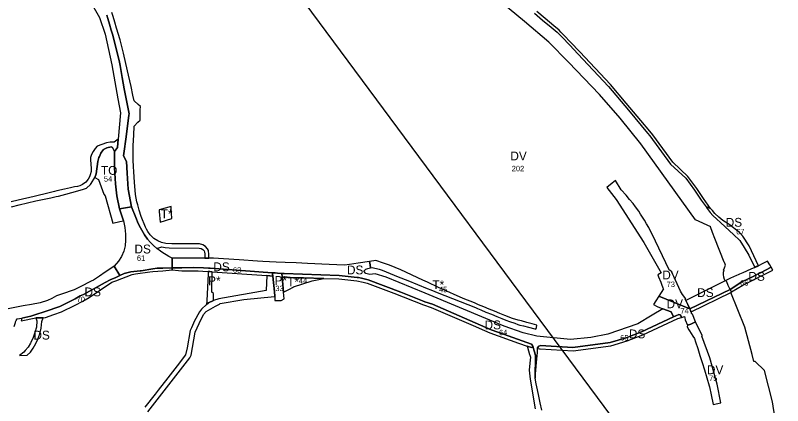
# Model space of a CAD drawing. Extents: x -535435 to -532834, y -1165802 to -1163866.
# Drawn here: x -534109 to -532979, y -1165015 to -1164441 of the extents above; entities that cross this region are included whole.
import ezdxf

# ---------------------------------------------------------------- set-up
doc = ezdxf.new("R2010")
doc.units = 0
for name, color, linetype in [('Level 14', 7, 'Continuous'), ('Level 15', 7, 'Continuous'), ('Level 22', 7, 'Continuous'), ('Level 23', 7, 'Continuous'), ('Level 35', 7, 'Continuous'), ('Level 4', 7, 'Continuous'), ('Level 43', 7, 'Continuous'), ('Level 44', 7, 'Continuous'), ('Level 5', 7, 'Continuous'), ('Level 61', 7, 'Continuous'), ('Level 62', 7, 'Continuous')]:
    doc.layers.add(name, color=color, linetype=linetype)

msp = doc.modelspace()

# ---------------------------------------------------------------- linework, layer by layer
at = {"layer": 'Level 14'}
for points in [[(-533157.8, -1164819.3), (-533163, -1164822.5), (-533161.8, -1164825.5), (-533158.7, -1164833.2), (-533157, -1164837.5), (-533154.9, -1164842.7), (-533154.8, -1164843.1), (-533161.7, -1164853.8), (-533116, -1164872.2), (-533119, -1164865.8), (-533121.8, -1164860.1), (-533122.6, -1164858.4), (-533121.9, -1164858.1), (-533122.4, -1164857), (-533124.5, -1164853.6), (-533126.8, -1164851.2), (-533129.8, -1164846.5), (-533139.4, -1164824.7), (-533143.2, -1164816.8), (-533143.6, -1164816.3), (-533144.3, -1164816), (-533144.6, -1164815.9), (-533145.2, -1164816), (-533145.7, -1164816), (-533171.8, -1164761.4), (-533174.1, -1164756.9), (-533176.4, -1164752.7), (-533179.5, -1164747.3), (-533182.7, -1164741.9), (-533185.3, -1164737.6), (-533188.4, -1164732.9), (-533191.1, -1164728.8), (-533195.7, -1164722.5), (-533199.4, -1164717.5), (-533204.4, -1164711.3), (-533209.4, -1164705.3), (-533216.8, -1164697.2), (-533225.2, -1164683.8), (-533230.1, -1164687.7), (-533238.1, -1164694.1), (-533224.1, -1164711.6), (-533183.3, -1164774.7), (-533157.8, -1164819.3)], [(-533128.7, -1164883.8), (-533127.9, -1164885.1), (-533123.8, -1164883.9), (-533123.2, -1164885.5), (-533122.9, -1164888.8), (-533119.4, -1164896.4), (-533114.4, -1164894.8), (-533107.5, -1164891.5), (-533111.8, -1164880.4), (-533113, -1164880.4), (-533113.9, -1164876.6), (-533114.4, -1164876.7), (-533114.8, -1164874.6), (-533116, -1164872.2), (-533161.7, -1164853.8), (-533166.1, -1164860.6), (-533169.3, -1164865.8), (-533163.8, -1164869.1), (-533155.4, -1164872.4), (-533143.4, -1164877), (-533140, -1164884.3), (-533136.5, -1164882.7), (-533131.8, -1164880.8), (-533130.3, -1164881.4), (-533128.7, -1164883.8)], [(-533114.4, -1164894.8), (-533119.4, -1164896.4), (-533119.8, -1164898.8), (-533117.1, -1164903.2), (-533116.1, -1164904.8), (-533111.3, -1164912.7), (-533109, -1164916.2), (-533107.5, -1164920.9), (-533104.3, -1164930.9), (-533100.9, -1164941.1), (-533097.7, -1164951.2), (-533094.4, -1164962.4), (-533090.9, -1164974.1), (-533087.4, -1164985.8), (-533086.9, -1164987.3), (-533084.4, -1164999), (-533081.3, -1165013.3), (-533070.4, -1165010.8), (-533075.7, -1164983.3), (-533086.4, -1164944.6), (-533098.1, -1164912.4), (-533097.9, -1164912.1), (-533097.9, -1164911.7), (-533107.5, -1164891.5), (-533114.4, -1164894.8)]]:
    msp.add_lwpolyline(points, dxfattribs=at)
at = {"layer": 'Level 15'}
for points in [[(-533682.6, -1164422.5), (-533200.4, -1165073.2)], [(-532979.2, -1165103.8), (-532994.2, -1165009), (-533005.9, -1164963.1), (-533019.7, -1164949.8), (-533021.6, -1164949.8), (-533024.3, -1164939.5), (-533035, -1164899.4), (-533055.7, -1164848.2), (-533054.7, -1164847.5), (-533056.5, -1164843.9), (-533059.2, -1164838), (-533061.6, -1164832.9), (-533061.9, -1164832.2), (-533062.2, -1164831.9), (-533062.6, -1164831.5), (-533063, -1164831.4), (-533063.6, -1164831.4), (-533064.6, -1164829.3), (-533065.9, -1164825.9), (-533066.3, -1164821.8), (-533066.1, -1164818.4), (-533065.5, -1164815.5), (-533066.1, -1164815.3), (-533065, -1164812.3), (-533063.4, -1164808), (-533063.8, -1164806.8), (-533064.8, -1164804.1), (-533065.3, -1164803.8), (-533079, -1164768.7), (-533082.4, -1164760), (-533085.4, -1164751.9), (-533085.1, -1164751.8), (-533107.7, -1164741.3), (-533187.9, -1164629.8), (-533218.6, -1164591.9), (-533248.9, -1164557.2), (-533294.4, -1164509.7), (-533323.6, -1164480.2), (-533359.3, -1164449.4), (-533393, -1164421.7)]]:
    msp.add_lwpolyline(points, dxfattribs=at)
at = {"layer": 'Level 22'}
msp.add_lwpolyline([(-533895.6, -1164744.9), (-533878.2, -1164739.7), (-533879.3, -1164723.8), (-533879.5, -1164721.7), (-533897, -1164726.7), (-533896.8, -1164729.2), (-533895.6, -1164744.9)], dxfattribs=at)
at = {"layer": 'Level 23'}
for points in [[(-533541.2, -1164814.8), (-533558, -1164808.3), (-533563.9, -1164806), (-533566.5, -1164805), (-533577.8, -1164801.3), (-533587.3, -1164802.7), (-533586.5, -1164807.8), (-533585.8, -1164812.2), (-533583.6, -1164811.6), (-533573.3, -1164813.9), (-533568.8, -1164815.7), (-533545.2, -1164825.2), (-533531.1, -1164830.9), (-533502.4, -1164842.5), (-533497.2, -1164844.5), (-533491.2, -1164846.9), (-533487.7, -1164848.3), (-533431.5, -1164870.6), (-533428.4, -1164871.8), (-533423.5, -1164873.9), (-533415.9, -1164877.1), (-533408, -1164880.3), (-533400.1, -1164883.6), (-533392.6, -1164886.7), (-533386.5, -1164889.3), (-533381.4, -1164891), (-533373.5, -1164893.7), (-533369.1, -1164895.3), (-533366, -1164896.3), (-533360.9, -1164897.6), (-533353.2, -1164899.6), (-533343.8, -1164902), (-533342.3, -1164902.3), (-533341.7, -1164900), (-533340.8, -1164896.5), (-533348, -1164894.6), (-533355.6, -1164892.4), (-533363.8, -1164890.2), (-533368.5, -1164888.9), (-533376.8, -1164886.6), (-533387.9, -1164882.2), (-533395.4, -1164879.2), (-533403.4, -1164875.9), (-533411.2, -1164872.7), (-533418.9, -1164869.5), (-533426.8, -1164866.3), (-533432.8, -1164863.8), (-533449.3, -1164857), (-533482.5, -1164842.7), (-533486, -1164841.2), (-533502.2, -1164833.4), (-533508.9, -1164830.2)], [(-533700.8, -1164841.2), (-533699, -1164840.2), (-533671.6, -1164831.2), (-533654.5, -1164827.9), (-533684.5, -1164827), (-533699.2, -1164826.6), (-533708.7, -1164825.9), (-533716.1, -1164825.2), (-533716.1, -1164825.6), (-533715.5, -1164831), (-533713.8, -1164847.9), (-533704.3, -1164843)]]:
    msp.add_lwpolyline(points, close=True, dxfattribs=at)
for points in [[(-533913.8, -1165024), (-533851.8, -1164944.7), (-533849.7, -1164940.5), (-533844, -1164906.5), (-533838.2, -1164893.8), (-533831.5, -1164880.8), (-533827.7, -1164876.4), (-533824.4, -1164874.4), (-533814.1, -1164868.4), (-533808.3, -1164865.4), (-533807.2, -1164864.8), (-533772.1, -1164858.7), (-533727.2, -1164854.1), (-533726.9, -1164854), (-533727.1, -1164847.2), (-533729.7, -1164824.1), (-533738.7, -1164823.4), (-533739.5, -1164845.6), (-533809.3, -1164857.5), (-533817.2, -1164860), (-533824.2, -1164863.4), (-533827.2, -1164866), (-533834.5, -1164872.8), (-533837.8, -1164876.6), (-533845.2, -1164891.1), (-533846.2, -1164893.4), (-533849.3, -1164900.2), (-533851.2, -1164904.2), (-533855.5, -1164929.8), (-533858.2, -1164940.3), (-533870.5, -1164956.3), (-533884.3, -1164974.1), (-533898.2, -1164991.9), (-533902.8, -1164997.8), (-533918, -1165017.2)], [(-533333.9, -1165021.4), (-533336.2, -1165010.6), (-533338.2, -1165000.7), (-533340.1, -1164991.5), (-533340.1, -1164991.4), (-533341.9, -1164982.7), (-533343.6, -1164974.3), (-533343.3, -1164963.3), (-533343.1, -1164953), (-533342.9, -1164942.2), (-533342.8, -1164941), (-533344.5, -1164935.7), (-533345.5, -1164932.6), (-533346.6, -1164929), (-533349, -1164929.4), (-533355.4, -1164927.2), (-533354.9, -1164928.8), (-533353.4, -1164934.1), (-533351.9, -1164939.4), (-533351.3, -1164940.6), (-533350.5, -1164943.4), (-533351.3, -1164952.5), (-533352.3, -1164962.6), (-533350.7, -1164975.8), (-533343.4, -1165019.3)]]:
    msp.add_lwpolyline(points, dxfattribs=at)
at = {"layer": 'Level 35'}
msp.add_lwpolyline([(-533965.3, -1164746.5), (-533954.8, -1164744.1), (-533949.6, -1164742.7), (-533955.1, -1164725.1), (-533959.3, -1164706.1), (-533961.1, -1164688.5), (-533962.5, -1164664.9), (-533962.8, -1164640.9), (-533965.8, -1164634.9), (-533967.7, -1164634.1), (-533974.1, -1164635.7), (-533978.8, -1164638.2), (-533981.7, -1164641.9), (-533982.7, -1164643.3), (-533984.8, -1164648.1), (-533985.6, -1164649.9), (-533987.1, -1164655.7), (-533989.6, -1164674), (-533991.8, -1164679.4), (-533986.3, -1164682.3), (-533978.2, -1164703.6), (-533976.6, -1164706.2)], close=True, dxfattribs=at)
at = {"layer": 'Level 4'}
for points in [[(-533999.9, -1164416.7), (-533984.7, -1164443.9), (-533976.4, -1164468.5), (-533966.5, -1164513.4), (-533957.7, -1164563.2), (-533953.9, -1164584.2), (-533957.2, -1164622.7), (-533958.2, -1164634.9), (-533962.8, -1164640.9), (-533962.5, -1164664.9), (-533961.1, -1164688.5), (-533959.3, -1164706.1), (-533955.1, -1164725.1), (-533937.6, -1164722.1), (-533942.5, -1164696.4), (-533942.9, -1164688.7), (-533943.8, -1164672.8), (-533944.8, -1164655.5), (-533949.2, -1164647.3), (-533948.7, -1164643.8), (-533945.6, -1164619.4), (-533941.6, -1164587.6), (-533941.3, -1164585.4), (-533948.6, -1164548.8), (-533951.4, -1164531.9), (-533954.4, -1164514.2), (-533955.2, -1164509.4), (-533962.7, -1164479.5), (-533965.5, -1164468.5), (-533967.4, -1164462.2), (-533970.1, -1164453.5), (-533972.7, -1164445.1), (-533974.2, -1164440.1)], [(-533092, -1164722.5), (-533088.7, -1164723.5), (-533085.2, -1164724.6), (-533095.7, -1164710.1), (-533105.4, -1164695.3), (-533118.6, -1164677.5), (-533141.1, -1164656.7), (-533170.5, -1164616.2), (-533174.7, -1164611.1), (-533188, -1164595.1), (-533209.4, -1164569.6), (-533232.5, -1164542.4), (-533277.6, -1164494.1), (-533291.3, -1164479.8), (-533300.6, -1164470.2), (-533305.5, -1164465.1), (-533308.4, -1164462.2), (-533315.9, -1164455.9), (-533328.8, -1164445.2), (-533340.8, -1164435.1)], [(-533344.4, -1164437.6), (-533332.5, -1164447.6), (-533320, -1164457.9), (-533311.3, -1164465.2), (-533309.6, -1164467), (-533304.4, -1164472.4), (-533292.7, -1164484.5), (-533280.6, -1164497), (-533235.7, -1164545.2), (-533205.9, -1164580.3), (-533177.9, -1164613.7), (-533174.6, -1164617.7), (-533144.2, -1164659.5), (-533121.7, -1164680.3), (-533108.9, -1164697.7), (-533099.2, -1164712.5), (-533092, -1164722.5)], [(-534067.7, -1164885.4), (-534078.3, -1164885.8), (-534077, -1164890.2), (-534077.7, -1164899.3), (-534079.8, -1164907), (-534082.4, -1164914.6), (-534085.7, -1164921.9), (-534086.5, -1164923.1), (-534089.9, -1164928.7), (-534094, -1164933.8), (-534095.9, -1164936), (-534102.6, -1164940.9), (-534091.4, -1164940.5), (-534086.4, -1164936.4), (-534082.2, -1164930.5), (-534078.3, -1164923.3), (-534075.5, -1164917), (-534072.8, -1164909.2), (-534070.4, -1164900.7), (-534069.4, -1164890.9), (-534067.7, -1164885.4)]]:
    msp.add_lwpolyline(points, dxfattribs=at)
for points in [[(-533872.6, -1164797.7), (-533877.6, -1164797.7), (-533877.6, -1164812.2), (-533863.4, -1164811.9), (-533845.9, -1164811.5), (-533831.8, -1164811.9), (-533824.1, -1164812.4), (-533821.7, -1164812.6), (-533730.5, -1164819.2), (-533726, -1164819.6), (-533722.7, -1164819.8), (-533716.6, -1164820.2), (-533712.8, -1164820.5), (-533632, -1164823.5), (-533605.3, -1164826.1), (-533603.5, -1164826.4), (-533598.9, -1164827.3), (-533593.1, -1164828.7), (-533589.2, -1164829.8), (-533541, -1164848), (-533509.4, -1164860.7), (-533506.1, -1164862), (-533494.7, -1164865.5), (-533408.4, -1164903.2), (-533390.2, -1164909.9), (-533349.1, -1164924.4), (-533347.4, -1164926.2), (-533346.6, -1164929), (-533345.5, -1164932.6), (-533344.5, -1164935.7), (-533342.8, -1164941), (-533342.9, -1164942.2), (-533343.1, -1164953), (-533343.3, -1164963.3), (-533343.6, -1164974.3), (-533342.6, -1164962.6), (-533341.5, -1164951.4), (-533340.5, -1164941.4), (-533340.3, -1164936.3), (-533340.2, -1164934.1), (-533340.1, -1164930.7), (-533340, -1164929.7), (-533338.3, -1164927.4), (-533335.4, -1164926.4), (-533288, -1164929.4), (-533233.2, -1164922.1), (-533209.6, -1164915), (-533186.9, -1164906.1), (-533140, -1164884.3), (-533143.4, -1164877), (-533155.4, -1164872.4), (-533171.4, -1164881.7), (-533192.2, -1164894.5), (-533236.4, -1164909.7), (-533261.6, -1164914.4), (-533291.3, -1164917.3), (-533340.8, -1164912.7), (-533361.3, -1164907.5), (-533389.2, -1164897.7), (-533410.4, -1164889), (-533505.4, -1164849.2), (-533562.7, -1164826), (-533578.9, -1164821.1), (-533586.7, -1164821.8), (-533592.6, -1164820.3), (-533595.6, -1164816.8), (-533592.9, -1164814.1), (-533589.9, -1164813.3), (-533585.8, -1164812.2), (-533586.5, -1164807.8), (-533587.3, -1164802.7), (-533603.8, -1164805.2), (-533616.7, -1164807), (-533624.2, -1164808), (-533646.8, -1164807), (-533678.4, -1164805.7), (-533695.1, -1164804.9), (-533711.4, -1164804.2), (-533724.5, -1164803.6), (-533744.2, -1164802.8), (-533752.3, -1164802.4), (-533779.2, -1164800.5), (-533802.4, -1164798.8), (-533817, -1164797.8), (-533820.6, -1164797.8), (-533823.2, -1164797.7), (-533829.7, -1164797.7), (-533845.8, -1164797.7), (-533863.7, -1164797.7)], [(-533121.8, -1164860.1), (-533119, -1164865.8), (-533116, -1164872.2), (-533056.5, -1164843.9), (-533039.3, -1164832.6), (-533021.8, -1164824.2), (-533013.1, -1164820), (-533011.7, -1164819.2), (-532996.3, -1164811.1), (-532998.2, -1164807.9), (-533001.7, -1164802.2), (-533009.4, -1164806.2), (-533015, -1164809.1), (-533017.5, -1164810.2), (-533020.2, -1164811.4), (-533026.2, -1164814.1), (-533037.9, -1164819.4), (-533042.8, -1164821.6), (-533044.7, -1164822.4), (-533047.2, -1164823.5), (-533055.9, -1164827.4), (-533063.6, -1164831.4)]]:
    msp.add_lwpolyline(points, close=True, dxfattribs=at)
at = {"layer": 'Level 43'}
for points in [[(-534110.3, -1164898.3), (-534108.4, -1164892.4), (-534108.2, -1164891.7), (-534107.6, -1164889.8), (-534106.1, -1164887.3), (-534099.3, -1164885.9), (-534085.8, -1164883.2), (-534079.8, -1164881.2), (-534064.7, -1164876.2), (-534042.9, -1164869), (-534020.7, -1164857.7), (-534013.4, -1164853.5), (-534008.1, -1164851.2), (-533976.6, -1164833.5), (-533969.1, -1164829.7), (-533960.9, -1164826.1), (-533954.9, -1164823.5), (-533963.1, -1164809.6), (-533973.8, -1164816.8), (-533976.3, -1164818.5), (-533985, -1164824.4), (-533993.8, -1164830.3), (-533996.8, -1164831.8), (-534013, -1164839.9), (-534021.8, -1164844.3), (-534040.7, -1164850.7), (-534047.9, -1164853.2), (-534055.1, -1164857.4), (-534061.3, -1164860.1), (-534072.3, -1164863.7), (-534084.7, -1164866), (-534096.9, -1164868.2), (-534121.6, -1164872.7)], [(-533819.6, -1164847.9), (-533818.8, -1164817.8), (-533822.2, -1164817.6), (-533823, -1164817.5), (-533824.6, -1164817.4), (-533824.9, -1164820.8), (-533826.9, -1164860.6), (-533827.2, -1164866), (-533824.2, -1164863.4), (-533817.2, -1164860), (-533817.1, -1164849.8), (-533819.6, -1164847.9)]]:
    msp.add_lwpolyline(points, dxfattribs=at)
at = {"layer": 'Level 44'}
msp.add_lwpolyline([(-533730.5, -1164819.2), (-533730, -1164821.1), (-533729.7, -1164824.1), (-533727.1, -1164847.2), (-533726.9, -1164854), (-533726.7, -1164859.2), (-533726.9, -1164860.2), (-533724, -1164860.2), (-533717.5, -1164860.1), (-533712.8, -1164857.6), (-533713.8, -1164847.9), (-533715.5, -1164831), (-533716.1, -1164825.6), (-533716.1, -1164825.2), (-533716.6, -1164820.2), (-533722.7, -1164819.8), (-533726, -1164819.6)], close=True, dxfattribs=at)
at = {"layer": 'Level 5'}
for points in [[(-533974.2, -1164440.1), (-533972.7, -1164445.1), (-533970.1, -1164453.5), (-533967.4, -1164462.2), (-533965.5, -1164468.5), (-533962.7, -1164479.5), (-533955.2, -1164509.4), (-533954.4, -1164514.2), (-533951.4, -1164531.9), (-533948.6, -1164548.8), (-533941.3, -1164585.4), (-533941.6, -1164587.6), (-533945.6, -1164619.4), (-533948.7, -1164643.8), (-533949.2, -1164647.3), (-533944.8, -1164655.5), (-533943.8, -1164672.8), (-533942.9, -1164688.7), (-533942.5, -1164696.4), (-533937.6, -1164722.1), (-533931.1, -1164738.2), (-533927.8, -1164746.6), (-533924.3, -1164753.3), (-533918.3, -1164763.7), (-533914, -1164769.7), (-533909.8, -1164774.7), (-533905.4, -1164779.1), (-533900.4, -1164783.5), (-533893.1, -1164781.3), (-533888.2, -1164782.1), (-533882, -1164782.6), (-533838.3, -1164783), (-533834.9, -1164783.6), (-533832.6, -1164785.1), (-533830.8, -1164787.2), (-533830, -1164789.1), (-533829.7, -1164791.7), (-533829.7, -1164797.7), (-533823.7, -1164797.7), (-533823.7, -1164792.5), (-533823.6, -1164791.3), (-533824.1, -1164787.5), (-533824.5, -1164786.6), (-533825.6, -1164784), (-533828.6, -1164780.5), (-533832.7, -1164778), (-533837.7, -1164777), (-533878.1, -1164776.6), (-533887.3, -1164776.2), (-533893.3, -1164774.7), (-533899, -1164772.3), (-533904.7, -1164768.7), (-533910.1, -1164763.7), (-533913.8, -1164758.8), (-533915.8, -1164755.1), (-533917.1, -1164752.1), (-533923.2, -1164736.3), (-533926.5, -1164727), (-533928.5, -1164719.6), (-533929.6, -1164715.2), (-533931.6, -1164704.2), (-533932.9, -1164692.1), (-533933.3, -1164686.3), (-533934.3, -1164670.1), (-533934.7, -1164663.4), (-533935.1, -1164653), (-533935.3, -1164642.9), (-533935, -1164632.2), (-533934.4, -1164616.8), (-533933.8, -1164603.6), (-533928.2, -1164597.9), (-533925, -1164594.8), (-533924.7, -1164579.8), (-533924.6, -1164574.8), (-533928, -1164571.6), (-533933.9, -1164566.2), (-533935.5, -1164557.8), (-533938.3, -1164545.3), (-533942.1, -1164528.7), (-533946.1, -1164511.2), (-533949.6, -1164496.1), (-533954.4, -1164476.5), (-533959.5, -1164459.2), (-533962.1, -1164450.6), (-533964.7, -1164442.1), (-533966.5, -1164436.2)], [(-534114.5, -1164722.3), (-534102.9, -1164719.2), (-534078.7, -1164713.7), (-534056.6, -1164708.9), (-534048.5, -1164707.3), (-534045.3, -1164706.4), (-534034.2, -1164703.6), (-534025.4, -1164701.4), (-534019.9, -1164699.9), (-534008.5, -1164696.2), (-534004.1, -1164694.9), (-533998.2, -1164689.6), (-533997.2, -1164688), (-533991.8, -1164679.4), (-533989.6, -1164674), (-533987.1, -1164655.7), (-533985.6, -1164649.9), (-533984.8, -1164648.1), (-533982.7, -1164643.3), (-533981.7, -1164641.9), (-533978.8, -1164638.2), (-533974.1, -1164635.7), (-533967.7, -1164634.1), (-533965.8, -1164634.9), (-533962.8, -1164640.9), (-533958.2, -1164634.9), (-533957.2, -1164622.7), (-533963, -1164627.2), (-533969.3, -1164627.2), (-533974.6, -1164628.3), (-533988.1, -1164633.2), (-533991.3, -1164636.5), (-533994.2, -1164640.9), (-533996.4, -1164645.3), (-533997.9, -1164649.9), (-533997.9, -1164653.7), (-533997.3, -1164659.2), (-533996.9, -1164666.3), (-533997.1, -1164670.4), (-533998.5, -1164675.4), (-533999.6, -1164678), (-534001.2, -1164681.7), (-534004.9, -1164685.9), (-534010, -1164689.5), (-534013.7, -1164691.2), (-534017.2, -1164692.3), (-534021.6, -1164693.1), (-534027.6, -1164694.2), (-534036.3, -1164696.2), (-534047.6, -1164698.9), (-534050.9, -1164699.7), (-534058.6, -1164701.5), (-534080.7, -1164706.9), (-534104.7, -1164712.6), (-534114.9, -1164715.1)], [(-533954.9, -1164823.5), (-533948.3, -1164820.6), (-533938.5, -1164818.2), (-533924.7, -1164816.7), (-533923.3, -1164816.7), (-533906.2, -1164813.7), (-533900.1, -1164812.7), (-533891.7, -1164812.5), (-533877.6, -1164812.2), (-533877.6, -1164797.7), (-533882.7, -1164795.4), (-533893.1, -1164789), (-533895, -1164787.7), (-533900.4, -1164783.5), (-533905.4, -1164779.1), (-533909.8, -1164774.7), (-533914, -1164769.7), (-533918.3, -1164763.7), (-533924.3, -1164753.3), (-533927.8, -1164746.6), (-533931.1, -1164738.2), (-533937.6, -1164722.1), (-533955.1, -1164725.1), (-533949.6, -1164742.7), (-533947.7, -1164752.9), (-533946.5, -1164762.4), (-533946.3, -1164771.4), (-533947.1, -1164779.7), (-533949, -1164787.7), (-533952.3, -1164795.2), (-533956.9, -1164802.5), (-533963.1, -1164809.6), (-533954.9, -1164823.5)], [(-533070.5, -1164745.6), (-533063.9, -1164751.8), (-533051.6, -1164762.9), (-533042.4, -1164772.1), (-533035.7, -1164782.1), (-533028.9, -1164793.4), (-533020.2, -1164811.4), (-533015, -1164809.1), (-533028.6, -1164779.9), (-533037.8, -1164765.4), (-533042.7, -1164760.3), (-533057.7, -1164748.3), (-533059.3, -1164747.3), (-533067.1, -1164742.2), (-533073.2, -1164737.6), (-533078.8, -1164732.3), (-533082.7, -1164727.8), (-533085.2, -1164724.6), (-533088.7, -1164723.5), (-533092, -1164722.5), (-533090.2, -1164724.9), (-533085.8, -1164730.7), (-533081.8, -1164735.2), (-533076.2, -1164740.6), (-533070.5, -1164745.6)], [(-533877.6, -1164812.2), (-533891.7, -1164812.5), (-533900.1, -1164812.7), (-533906.2, -1164813.7), (-533923.3, -1164816.7), (-533924.7, -1164816.7), (-533938.5, -1164818.2), (-533948.3, -1164820.6), (-533954.9, -1164823.5), (-533960.9, -1164826.1), (-533969.1, -1164829.7), (-533976.6, -1164833.5), (-534008.1, -1164851.2), (-534013.4, -1164853.5), (-534020.7, -1164857.7), (-534042.9, -1164869), (-534064.7, -1164876.2), (-534079.8, -1164881.2), (-534085.8, -1164883.2), (-534099.3, -1164885.9), (-534099.9, -1164890), (-534078.3, -1164885.8), (-534067.7, -1164885.4), (-534064.4, -1164885.3), (-534051.9, -1164880.9), (-534040.7, -1164877), (-534020.4, -1164867.2), (-534009.5, -1164861.2), (-533999.8, -1164855.9), (-533966.4, -1164833.2), (-533960.8, -1164831), (-533936.5, -1164821.8), (-533931.8, -1164821.1), (-533910.9, -1164818.1), (-533906.2, -1164817.7), (-533891.7, -1164816.4), (-533877.6, -1164815.2), (-533877.6, -1164812.2)], [(-533877.6, -1164812.2), (-533877.6, -1164815.2), (-533868.7, -1164816), (-533863.5, -1164816.3), (-533854.1, -1164816.7), (-533846.1, -1164816.5), (-533839.7, -1164816.7), (-533832.6, -1164816.9), (-533824.9, -1164817.4), (-533824.7, -1164817.4), (-533824.6, -1164817.4), (-533823, -1164817.5), (-533822.2, -1164817.6), (-533818.8, -1164817.8), (-533738.7, -1164823.4), (-533729.7, -1164824.1), (-533730, -1164821.1), (-533730.5, -1164819.2), (-533821.7, -1164812.6), (-533824.1, -1164812.4), (-533831.8, -1164811.9), (-533845.9, -1164811.5), (-533863.4, -1164811.9), (-533877.6, -1164812.2)], [(-533012.9, -1164819.8), (-533013.1, -1164820), (-533021.8, -1164824.2), (-533039.3, -1164832.6), (-533056.5, -1164843.9), (-533116, -1164872.2), (-533114.8, -1164874.6), (-533114.4, -1164876.7), (-533113.9, -1164876.6), (-533055.7, -1164848.2), (-533054.7, -1164847.5), (-533037.7, -1164837.5), (-533037.4, -1164837.3), (-533036.8, -1164837), (-533019.4, -1164828.2), (-533011, -1164824), (-533010.3, -1164823.7), (-532993.6, -1164815.7), (-532996.3, -1164811.1), (-533011.7, -1164819.2), (-533012.9, -1164819.8)]]:
    msp.add_lwpolyline(points, dxfattribs=at)
for points in [[(-533425.9, -1164901), (-533410.2, -1164907.9), (-533368.1, -1164922.8), (-533355.4, -1164927.2), (-533349, -1164929.4), (-533346.6, -1164929), (-533347.4, -1164926.2), (-533349.1, -1164924.4), (-533390.2, -1164909.9), (-533408.4, -1164903.2), (-533494.7, -1164865.5), (-533506.1, -1164862), (-533509.4, -1164860.7), (-533541, -1164848), (-533589.2, -1164829.8), (-533593.1, -1164828.7), (-533598.9, -1164827.3), (-533603.5, -1164826.4), (-533605.3, -1164826.1), (-533632, -1164823.5), (-533712.8, -1164820.5), (-533716.6, -1164820.2), (-533716.1, -1164825.2), (-533708.7, -1164825.9), (-533699.2, -1164826.6), (-533684.5, -1164827), (-533654.5, -1164827.9), (-533632.4, -1164828.5), (-533605.8, -1164831.1), (-533596.5, -1164833.2), (-533590.8, -1164834.6), (-533551.4, -1164849.4), (-533507.7, -1164866.7), (-533496.4, -1164870.2), (-533431.1, -1164898.6)], [(-533127.9, -1164885.1), (-533130.3, -1164881.4), (-533131.8, -1164880.8), (-533136.5, -1164882.7), (-533140, -1164884.3), (-533186.9, -1164906.1), (-533209.6, -1164915), (-533233.2, -1164922.1), (-533288, -1164929.4), (-533335.4, -1164926.4), (-533338.3, -1164927.4), (-533340, -1164929.7), (-533340.1, -1164930.7), (-533337.2, -1164931.5), (-533335.9, -1164931.4), (-533287.8, -1164934.4), (-533232.1, -1164927), (-533208, -1164919.7), (-533184.9, -1164910.6), (-533133.3, -1164886.8)]]:
    msp.add_lwpolyline(points, close=True, dxfattribs=at)

# ---------------------------------------------------------------- texts
at = {"layer": 'Level 14'}
for p in [(-533156.4, -1164829.1), (-533150.1, -1164871.5), (-533090.7, -1164968.6)]:
    msp.add_text('DV', height=13, dxfattribs=at).set_placement(p)
at = {"layer": 'Level 15'}
msp.add_text('DV', height=13, dxfattribs=at).set_placement((-533380, -1164654))
at = {"layer": 'Level 22'}
msp.add_text('T*', height=13, dxfattribs=at).set_placement((-533894.7, -1164739.1))
at = {"layer": 'Level 23'}
for p in [(-533708.4, -1164839.2), (-533494.8, -1164843.4)]:
    msp.add_text('T*', height=13, dxfattribs=at).set_placement(p)
at = {"layer": 'Level 35'}
msp.add_text('TO', height=13, dxfattribs=at).set_placement((-533982.6, -1164675.2))
at = {"layer": 'Level 4'}
for p in [(-533620.5, -1164821.7), (-533105, -1164855), (-534082, -1164917.6)]:
    msp.add_text('DS', height=13, dxfattribs=at).set_placement(p)
at = {"layer": 'Level 43'}
msp.add_text('P*', height=13, dxfattribs=at).set_placement((-533824.9, -1164837.6))
at = {"layer": 'Level 44'}
msp.add_text('P*', height=13, dxfattribs=at).set_placement((-533727.1, -1164837.2))
at = {"layer": 'Level 5'}
for p in [(-533063, -1164751.6), (-533933.3, -1164790.9), (-533817.2, -1164817.1), (-533029.6, -1164831.1), (-534006.8, -1164854), (-533418, -1164902.6), (-533205.5, -1164915.8)]:
    msp.add_text('DS', height=13, dxfattribs=at).set_placement(p)
at = {"layer": 'Level 61'}
for s, p in [('54', (-533978.3, -1164685.2)), ('67', (-533047.7, -1164762.8)), ('61', (-533929.7, -1164801.8)), ('63', (-533788.4, -1164819.2)), ('44', (-533691.3, -1164835)), ('66', (-533041.9, -1164838.2)), ('33', (-533725.9, -1164846.3)), ('45', (-533485, -1164848)), ('73', (-533150, -1164840.3)), ('70', (-534018.5, -1164862.5)), ('74', (-533129.7, -1164879.4)), ('64', (-533396.7, -1164911.2)), ('65', (-533218.4, -1164919)), ('75', (-533087.5, -1164978.6))]:
    msp.add_text(s, height=8, dxfattribs=at).set_placement(p)
at = {"layer": 'Level 62'}
msp.add_text('202', height=8, dxfattribs=at).set_placement((-533378, -1164670))

doc.saveas('drawing.dxf')
